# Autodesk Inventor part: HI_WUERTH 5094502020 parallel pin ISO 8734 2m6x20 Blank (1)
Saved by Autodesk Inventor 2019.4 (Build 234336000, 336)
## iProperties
Created: 2021-06
Part Number: HI_WUERTH 5094502020 parallel pin ISO 8734 2m6x20 Blank (1)
Material: Generic
Document SubType Name: Modeling
Designer: Administrator
Density: 1 g/cm^3
Appearance: Default
Title: HI_WUERTH 5094502020 parallel pin ISO 8734 2m6x20 Blank (1)
Author: Administrator
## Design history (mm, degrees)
feature "Body1"
body "Solid1"
